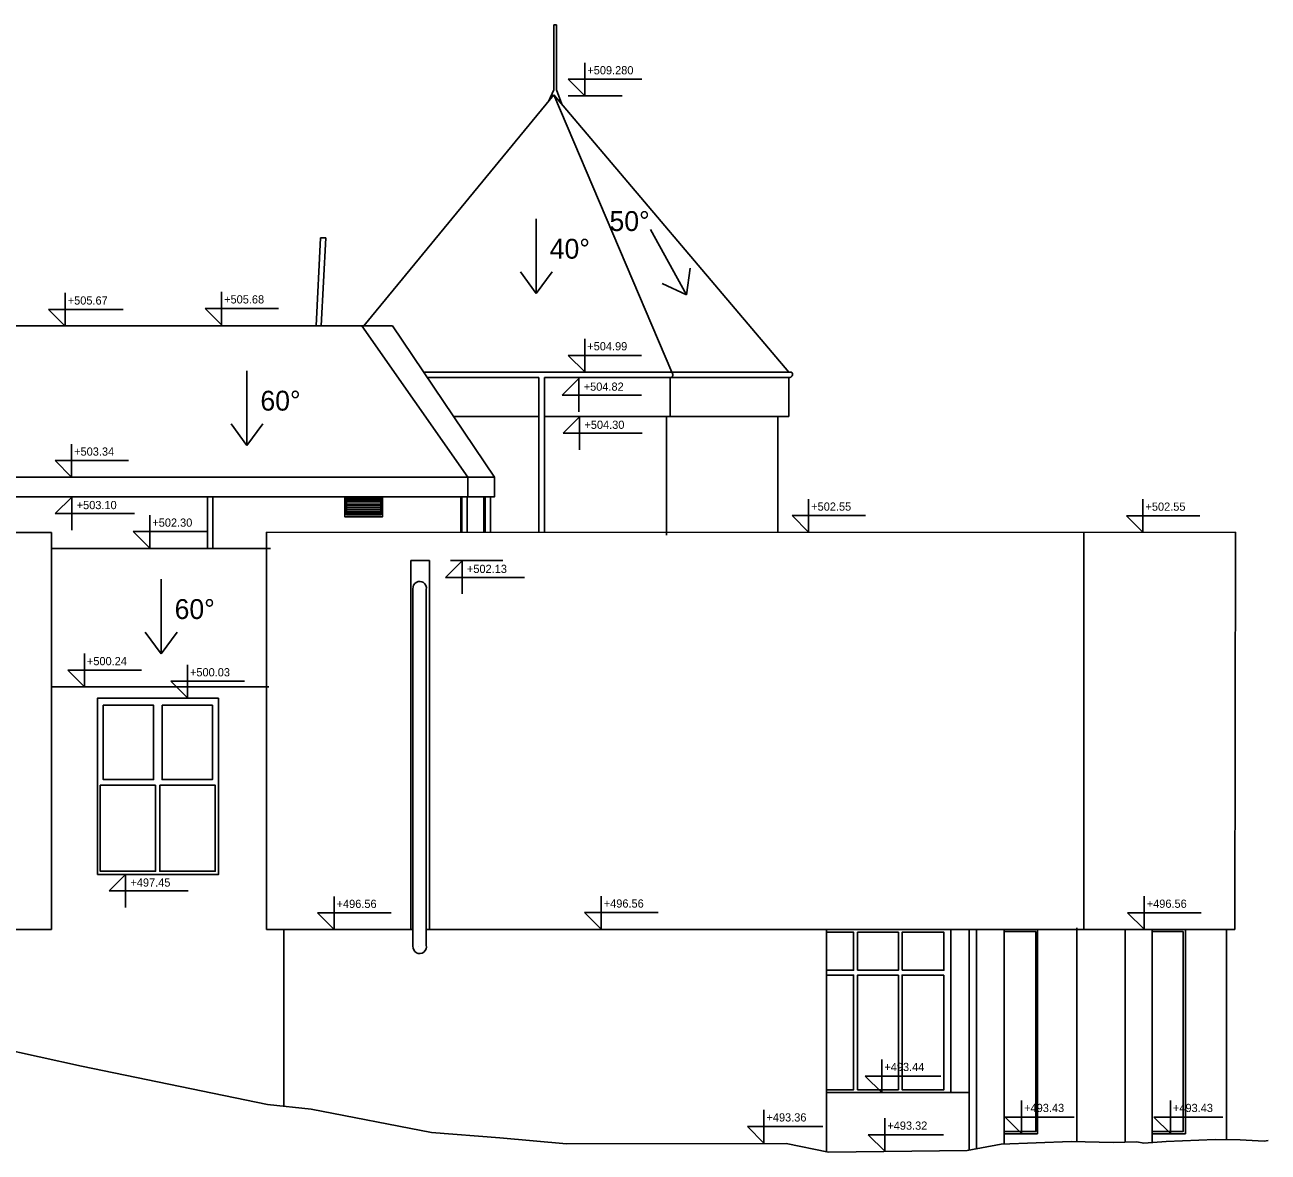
# Model space of a CAD drawing. Extents: x 96.5 to 160.8, y 493.2 to 511.4.
# Drawn here: x 141.98 to 160.77, y 493.2 to 510.23 of the extents above; entities that cross this region are included whole.
import ezdxf

# ---------------------------------------------------------------- set-up
doc = ezdxf.new("R2010")
doc.units = 0
for name, color, linetype in [('antena', 7, 'Continuous'), ('okap', 7, 'Continuous'), ('okna', 7, 'Continuous'), ('strecha_sikma', 7, 'Continuous'), ('teren', 7, 'Continuous'), ('vyustky_vzduchotechniky', 7, 'Continuous'), ('zakl_tenka', 7, 'Continuous'), ('znaceni', 7, 'Continuous')]:
    doc.layers.add(name, color=color, linetype=linetype)

msp = doc.modelspace()

# ---------------------------------------------------------------- linework, layer by layer
at = {"layer": 'antena'}
for p, q in [((149.974, 509.247), (149.974, 510.227)), ((150.014, 510.227), (149.974, 510.227)), ((150.014, 510.227), (150.014, 509.247)), ((149.892, 509.07), (149.974, 509.247)), ((150.014, 509.247), (150.094, 509.029)), ((146.452, 507.013), (146.382, 505.68)), ((146.452, 507.013), (146.532, 507.013)), ((146.532, 507.013), (146.462, 505.68))]:
    msp.add_line(p, q, dxfattribs=at)
at = {"layer": 'okap'}
for p, q in [((153.567, 504.983), (148.014, 504.983)), ((148.069, 504.9), (149.75, 504.9)), ((149.832, 504.9), (153.527, 504.9)), ((147.846, 501.71), (147.846, 496.315)), ((148.048, 501.703), (148.048, 496.332)), ((147.936, 496.307), (147.936, 496.307))]:
    msp.add_line(p, q, dxfattribs=at)
for points in [[(149.75, 502.566), (149.75, 504.9)], [(149.832, 504.9), (149.832, 502.566)], [(144.745, 503.098), (144.745, 502.319)], [(144.825, 502.319), (144.825, 503.098)], [(148.585, 503.098), (148.585, 502.566)], [(148.666, 502.566), (148.666, 503.098)], [(148.938, 503.098), (148.938, 502.566)], [(149.019, 502.566), (149.019, 503.098)]]:
    msp.add_lwpolyline(points, dxfattribs=at)
for points in [[(148.677, 503.395), (127.176, 503.395), (127.176, 503.098), (148.677, 503.098)], [(149.078, 503.395), (148.677, 503.395), (148.677, 503.098), (149.078, 503.098)]]:
    msp.add_lwpolyline(points, close=True, dxfattribs=at)
for centre, radius, start, end in [((151.725, 504.946), 0.047, 279.5595, 50.6672), ((153.531, 504.949), 0.0495, 265.6915, 42.3934), ((147.948, 501.721), 0.102, 349.5892, 186.5624), ((147.948, 496.307), 0.103, 175.4308, 13.9011)]:
    msp.add_arc(centre, radius, start, end, dxfattribs=at)
at = {"layer": 'okna'}
msp.add_line((155.973, 496.567), (155.973, 494.103), dxfattribs=at)
for points in [[(143.167, 499.954), (143.927, 499.954), (143.927, 498.83), (143.167, 498.83)], [(144.056, 499.954), (144.818, 499.954), (144.818, 498.83), (144.056, 498.83)], [(143.958, 498.744), (143.122, 498.744), (143.122, 497.447), (143.958, 497.447)], [(144.021, 498.744), (144.859, 498.744), (144.859, 497.447), (144.021, 497.447)], [(154.563, 495.951), (155.18, 495.951), (155.18, 496.526), (154.563, 496.526)], [(155.236, 495.951), (155.869, 495.951), (155.869, 496.526), (155.236, 496.526)], [(155.18, 495.877), (154.563, 495.877), (154.563, 494.146), (155.18, 494.146)], [(155.869, 495.877), (155.236, 495.877), (155.236, 494.146), (155.869, 494.146)]]:
    msp.add_lwpolyline(points, close=True, dxfattribs=at)
for points in [[(154.093, 495.951), (154.504, 495.951), (154.504, 496.526), (154.093, 496.526)], [(156.779, 493.515), (157.256, 493.515), (157.256, 496.536), (156.779, 496.536)], [(159.015, 496.536), (159.481, 496.536), (159.481, 493.516), (159.015, 493.516)], [(154.093, 494.146), (154.504, 494.146), (154.504, 495.877), (154.093, 495.877)]]:
    msp.add_lwpolyline(points, dxfattribs=at)
at = {"layer": 'strecha_sikma'}
for p, q in [((149.974, 509.17), (147.102, 505.681)), ((149.974, 509.17), (151.755, 504.983)), ((149.974, 509.17), (153.527, 504.983)), ((128.011, 505.68), (147.075, 505.68)), ((147.075, 505.68), (148.677, 503.395)), ((147.536, 505.68), (147.075, 505.68)), ((147.536, 505.68), (149.078, 503.395)), ((148.677, 503.395), (127.176, 503.395)), ((145.696, 502.319), (142.384, 502.319)), ((145.67, 500.233), (142.384, 500.233))]:
    msp.add_line(p, q, dxfattribs=at)
at = {"layer": 'teren'}
for p, q in [((140.434, 495.034), (142.837, 494.503)), ((142.837, 494.503), (145.647, 493.925)), ((145.647, 493.925), (146.31, 493.853)), ((146.31, 493.853), (148.127, 493.502)), ((148.127, 493.502), (149.159, 493.423)), ((149.159, 493.423), (150.168, 493.328)), ((150.168, 493.328), (153.486, 493.337)), ((153.486, 493.337), (154.122, 493.205)), ((154.122, 493.205), (156.217, 493.228)), ((156.217, 493.228), (156.732, 493.323)), ((156.732, 493.323), (157.789, 493.365)), ((157.789, 493.365), (158.423, 493.351)), ((158.423, 493.351), (158.78, 493.361)), ((158.78, 493.361), (158.889, 493.342)), ((158.889, 493.342), (159.224, 493.364)), ((159.224, 493.364), (159.968, 493.395)), ((159.968, 493.395), (160.344, 493.388)), ((160.344, 493.388), (160.707, 493.371)), ((160.707, 493.371), (160.766, 493.381))]:
    msp.add_line(p, q, dxfattribs=at)
at = {"layer": 'vyustky_vzduchotechniky'}
for p, q in [((146.843, 503.077), (147.359, 503.077)), ((146.843, 503.05), (147.359, 503.05)), ((146.843, 503.023), (147.359, 503.023)), ((146.843, 502.991), (147.359, 502.991)), ((146.843, 502.964), (147.359, 502.964)), ((146.843, 502.932), (147.359, 502.932)), ((146.843, 502.905), (147.359, 502.905)), ((146.843, 502.874), (147.359, 502.874)), ((146.843, 502.847), (147.359, 502.847))]:
    msp.add_line(p, q, dxfattribs=at)
for points in [[(147.387, 503.098), (147.387, 502.8), (146.815, 502.8), (146.815, 503.098)], [(147.359, 503.098), (147.359, 502.826), (146.843, 502.826), (146.843, 503.098)]]:
    msp.add_lwpolyline(points, dxfattribs=at)
at = {"layer": 'zakl_tenka'}
for p, q in [((149.75, 504.9), (148.069, 504.9)), ((151.733, 504.9), (149.832, 504.9)), ((153.527, 504.9), (151.733, 504.9)), ((151.733, 504.9), (151.733, 504.312)), ((153.527, 504.312), (153.527, 504.9)), ((149.75, 504.312), (148.463, 504.312)), ((151.677, 504.312), (149.832, 504.312)), ((151.677, 502.522), (151.677, 504.312)), ((151.677, 504.312), (153.527, 504.312)), ((153.357, 504.312), (153.357, 502.564)), ((148.571, 503.098), (148.571, 502.566)), ((148.917, 503.098), (148.917, 502.566)), ((142.384, 502.56), (135.698, 502.56)), ((142.384, 502.56), (142.384, 496.567)), ((145.632, 496.567), (145.632, 502.568)), ((145.632, 502.568), (157.983, 502.562)), ((157.982, 496.567), (157.983, 502.562)), ((160.273, 502.567), (157.983, 502.562)), ((160.263, 496.567), (160.273, 502.567)), ((147.815, 502.138), (148.096, 502.138)), ((147.815, 502.138), (147.815, 496.567)), ((148.096, 502.138), (148.096, 496.567)), ((142.384, 496.567), (135.702, 496.567)), ((147.846, 496.567), (145.632, 496.567)), ((145.897, 496.567), (145.897, 493.898)), ((157.982, 496.567), (148.048, 496.567)), ((154.093, 496.567), (154.093, 493.211)), ((156.247, 496.567), (156.247, 493.234)), ((156.362, 493.255), (156.362, 496.567)), ((156.779, 496.567), (156.779, 493.325)), ((157.284, 496.567), (157.284, 493.48)), ((157.875, 496.59), (157.875, 493.363)), ((160.263, 496.567), (157.982, 496.567)), ((158.605, 496.567), (158.605, 493.356)), ((159.015, 496.567), (159.015, 493.35)), ((159.52, 496.567), (159.52, 493.48)), ((160.139, 496.567), (160.139, 493.392)), ((156.247, 494.103), (154.093, 494.103)), ((157.284, 493.48), (156.779, 493.48)), ((159.52, 493.48), (159.015, 493.48))]:
    msp.add_line(p, q, dxfattribs=at)
msp.add_lwpolyline([(144.909, 500.062), (143.082, 500.062), (143.082, 497.399), (144.909, 497.399)], close=True, dxfattribs=at)
at = {"layer": 'znaceni'}
for p, q in [((150.442, 509.655), (150.442, 509.155)), ((150.442, 509.405), (150.192, 509.405)), ((150.192, 509.405), (150.442, 509.155)), ((150.442, 509.155), (150.442, 509.405)), ((150.442, 509.405), (151.302, 509.405)), ((150.192, 509.155), (151.009, 509.155)), ((149.709, 507.299), (149.709, 506.169)), ((151.435, 507.139), (151.98, 506.15)), ((149.709, 506.169), (149.469, 506.496)), ((149.709, 506.169), (149.95, 506.496)), ((151.98, 506.15), (152.033, 506.552)), ((144.956, 506.195), (144.956, 505.695)), ((151.98, 506.15), (151.611, 506.32)), ((142.592, 506.178), (142.592, 505.678)), ((142.592, 505.928), (142.342, 505.928)), ((142.342, 505.928), (142.592, 505.678)), ((142.592, 505.678), (142.592, 505.928)), ((142.592, 505.928), (143.468, 505.928)), ((144.956, 505.945), (144.706, 505.945)), ((144.706, 505.945), (144.956, 505.695)), ((144.956, 505.695), (144.956, 505.945)), ((144.956, 505.945), (145.817, 505.945)), ((150.442, 505.486), (150.442, 504.986)), ((150.442, 505.236), (150.192, 505.236)), ((150.192, 505.236), (150.442, 504.986)), ((150.442, 504.986), (150.442, 505.236)), ((150.442, 505.236), (151.301, 505.236)), ((145.338, 505.005), (145.338, 503.875)), ((150.103, 504.636), (150.353, 504.886)), ((150.353, 504.886), (150.353, 504.386)), ((150.353, 504.386), (150.353, 504.886)), ((150.353, 504.886), (150.353, 504.636)), ((150.353, 504.636), (150.103, 504.636)), ((150.353, 504.636), (150.103, 504.636)), ((150.353, 504.386), (150.353, 504.636)), ((150.353, 504.636), (151.299, 504.636)), ((150.353, 504.636), (151.299, 504.636)), ((150.114, 504.06), (150.364, 504.31)), ((150.364, 504.31), (150.364, 503.81)), ((150.364, 503.81), (150.364, 504.31)), ((150.364, 504.31), (150.364, 504.06)), ((145.338, 503.875), (145.098, 504.202)), ((145.338, 503.875), (145.579, 504.202)), ((150.364, 504.06), (150.114, 504.06)), ((150.364, 504.06), (150.114, 504.06)), ((150.364, 503.81), (150.364, 504.06)), ((150.364, 504.06), (151.31, 504.06)), ((150.364, 504.06), (151.31, 504.06)), ((142.689, 503.897), (142.689, 503.397)), ((142.689, 503.647), (142.439, 503.647)), ((142.439, 503.647), (142.689, 503.397)), ((142.689, 503.397), (142.689, 503.647)), ((142.689, 503.647), (143.549, 503.647)), ((142.443, 502.847), (142.693, 503.097)), ((142.693, 503.097), (142.693, 502.597)), ((142.693, 502.597), (142.693, 503.097)), ((142.693, 503.097), (142.693, 502.847)), ((153.824, 503.066), (153.824, 502.566)), ((158.874, 503.064), (158.874, 502.564)), ((142.693, 502.847), (142.443, 502.847)), ((142.693, 502.847), (142.443, 502.847)), ((142.693, 502.597), (142.693, 502.847)), ((142.693, 502.847), (143.639, 502.847)), ((142.693, 502.847), (143.639, 502.847)), ((143.87, 502.824), (143.87, 502.324)), ((153.824, 502.816), (153.574, 502.816)), ((153.574, 502.816), (153.824, 502.566)), ((153.824, 502.566), (153.824, 502.816)), ((153.824, 502.816), (154.685, 502.816)), ((158.874, 502.814), (158.624, 502.814)), ((158.624, 502.814), (158.874, 502.564)), ((158.874, 502.564), (158.874, 502.814)), ((158.874, 502.814), (159.736, 502.814)), ((143.87, 502.574), (143.62, 502.574)), ((143.62, 502.574), (143.87, 502.324)), ((143.87, 502.324), (143.87, 502.574)), ((143.87, 502.574), (144.731, 502.574)), ((148.339, 501.884), (148.589, 502.134)), ((148.412, 502.138), (149.204, 502.138)), ((148.589, 502.134), (148.589, 501.634)), ((148.589, 501.634), (148.589, 502.134)), ((148.589, 502.134), (148.589, 501.884)), ((148.589, 501.884), (148.339, 501.884)), ((148.589, 501.884), (148.339, 501.884)), ((148.589, 501.634), (148.589, 501.884)), ((148.589, 501.884), (149.534, 501.884)), ((148.589, 501.884), (149.534, 501.884)), ((144.042, 501.858), (144.042, 500.728)), ((144.042, 500.728), (143.801, 501.055)), ((144.042, 500.728), (144.283, 501.055)), ((142.882, 500.732), (142.882, 500.232)), ((144.439, 500.564), (144.439, 500.064)), ((142.882, 500.482), (142.632, 500.482)), ((142.632, 500.482), (142.882, 500.232)), ((142.882, 500.232), (142.882, 500.482)), ((142.882, 500.482), (143.744, 500.482)), ((144.439, 500.314), (144.189, 500.314)), ((144.189, 500.314), (144.439, 500.064)), ((144.439, 500.064), (144.439, 500.314)), ((144.439, 500.314), (145.301, 500.314)), ((143.255, 497.148), (143.505, 497.398)), ((143.505, 497.398), (143.505, 496.898)), ((143.505, 496.898), (143.505, 497.398)), ((143.505, 497.398), (143.505, 497.148)), ((143.505, 497.148), (143.255, 497.148)), ((143.505, 497.148), (143.255, 497.148)), ((143.505, 496.898), (143.505, 497.148)), ((143.505, 497.148), (144.45, 497.148)), ((143.505, 497.148), (144.45, 497.148)), ((146.654, 497.067), (146.654, 496.567)), ((150.69, 497.071), (150.69, 496.571)), ((158.893, 497.069), (158.893, 496.569)), ((146.654, 496.817), (146.404, 496.817)), ((146.404, 496.817), (146.654, 496.567)), ((146.654, 496.567), (146.654, 496.817)), ((146.654, 496.817), (147.515, 496.817)), ((150.69, 496.821), (150.44, 496.821)), ((150.44, 496.821), (150.69, 496.571)), ((150.69, 496.571), (150.69, 496.821)), ((150.69, 496.821), (151.551, 496.821)), ((158.893, 496.819), (158.643, 496.819)), ((158.643, 496.819), (158.893, 496.569)), ((158.893, 496.569), (158.893, 496.819)), ((158.893, 496.819), (159.755, 496.819)), ((154.93, 494.604), (154.93, 494.104)), ((154.93, 494.354), (154.68, 494.354)), ((154.68, 494.354), (154.93, 494.104)), ((154.93, 494.104), (154.93, 494.354)), ((154.93, 494.354), (155.819, 494.354)), ((157.041, 493.985), (157.041, 493.485)), ((159.289, 493.984), (159.289, 493.484)), ((153.148, 493.841), (153.148, 493.341)), ((154.974, 493.718), (154.974, 493.218)), ((157.041, 493.735), (156.791, 493.735)), ((156.791, 493.735), (157.041, 493.485)), ((157.041, 493.485), (157.041, 493.735)), ((157.041, 493.735), (157.835, 493.735)), ((159.289, 493.734), (159.039, 493.734)), ((159.039, 493.734), (159.289, 493.484)), ((159.289, 493.484), (159.289, 493.734)), ((159.289, 493.734), (160.083, 493.734)), ((153.148, 493.591), (152.898, 493.591)), ((152.898, 493.591), (153.148, 493.341)), ((153.148, 493.341), (153.148, 493.591)), ((153.148, 493.591), (154.037, 493.591)), ((154.974, 493.468), (154.724, 493.468)), ((154.724, 493.468), (154.974, 493.218)), ((154.974, 493.218), (154.974, 493.468)), ((154.974, 493.468), (155.864, 493.468))]:
    msp.add_line(p, q, dxfattribs=at)

# ---------------------------------------------------------------- texts
for s, height, p in [('+509.280', 0.124, (150.481, 509.48)), ('50°', 0.3, (150.816, 507.114)), ('40°', 0.3, (149.913, 506.696)), ('+505.67', 0.124, (142.631, 506.003)), ('+505.68', 0.124, (144.994, 506.02)), ('+504.99', 0.124, (150.48, 505.312)), ('60°', 0.3, (145.542, 504.402)), ('+504.82', 0.124, (150.426, 504.702)), ('+504.30', 0.124, (150.437, 504.126)), ('+503.34', 0.124, (142.728, 503.722)), ('+503.10', 0.124, (142.766, 502.914)), ('+502.55', 0.124, (153.863, 502.891)), ('+502.55', 0.124, (158.913, 502.89)), ('+502.30', 0.124, (143.909, 502.649)), ('+502.13', 0.124, (148.662, 501.95)), ('60°', 0.3, (144.246, 501.255)), ('+500.24', 0.124, (142.921, 500.557)), ('+500.03', 0.124, (144.478, 500.389)), ('+497.45', 0.124, (143.578, 497.214)), ('+496.56', 0.124, (146.693, 496.892)), ('+496.56', 0.124, (150.729, 496.897)), ('+496.56', 0.124, (158.932, 496.894)), ('+493.44', 0.124, (154.968, 494.429)), ('+493.36', 0.124, (153.187, 493.667)), ('+493.43', 0.124, (157.08, 493.81)), ('+493.43', 0.124, (159.328, 493.81)), ('+493.32', 0.124, (155.013, 493.543))]:
    msp.add_text(s, height=height, dxfattribs=at).set_placement(p)

doc.saveas('drawing.dxf')
